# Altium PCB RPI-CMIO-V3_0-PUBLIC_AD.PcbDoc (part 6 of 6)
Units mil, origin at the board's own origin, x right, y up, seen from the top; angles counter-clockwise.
Board outline 3295.4 x 4105.44 mil, 6 copper layers (TOP, GNDT, PWRT, PWRB, GNDB, BOTTOM); 114 components, 152 nets, 703 pads, 476 vias.
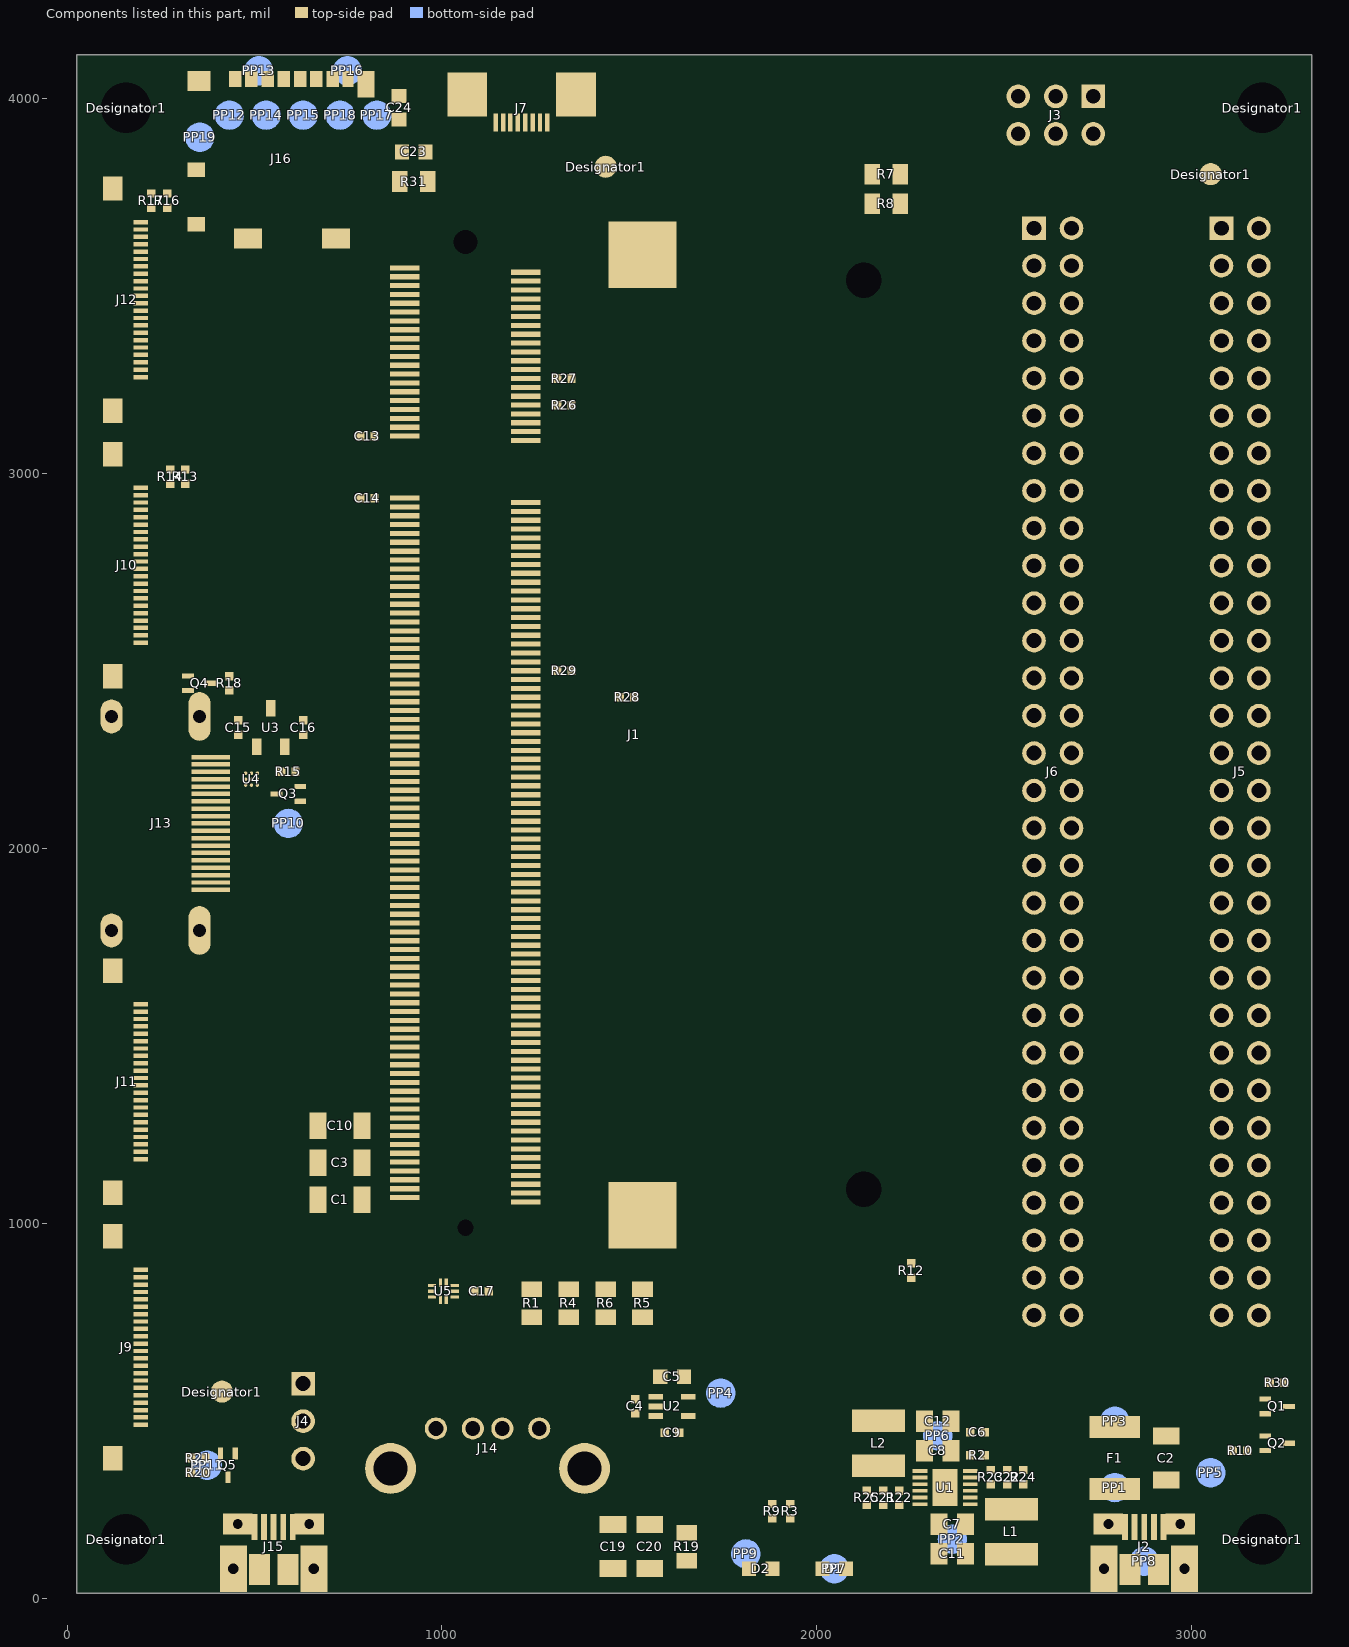
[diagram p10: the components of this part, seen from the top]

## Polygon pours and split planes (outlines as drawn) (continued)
CAM0_CN on BOTTOM "BOTTOM-CAM0_CN 1" (solid, pour order 1354): 1309.15,1716.41 ccw(c1310.77,1714.79) 1309.15,1713.18 1314.5,1707.84 1322.03,1714.79 1314.5,1721.75 1309.15,1716.41 ccw(c1310.77,1714.79)
DSI1_DN3 on BOTTOM "BOTTOM-DSI1_DN3" (solid, pour order 1355): 270.22,3516.35 ccw(c267.94,3516.35) 267.94,3518.63 260.38,3518.63 259.97,3508.39 270.22,3508.79 270.22,3516.35 ccw(c267.94,3516.35)
DSI1_DN3 on BOTTOM "BOTTOM-DSI1_DN3 1" (solid, pour order 1356): 1308.92,2141.63 ccw(c1310.53,2140.01) 1308.92,2138.4 1314.26,2133.05 1321.79,2140.01 1314.26,2146.97 1308.92,2141.63 ccw(c1310.53,2140.01)
GPIO20 on BOTTOM "BOTTOM-GPIO20" (solid, pour order 1357): 984.25,2594.49 ccw(c984.25,2598.43) 988.19,2598.43 988.19,2604.33 977.65,2605.03 978.35,2594.49 984.25,2594.49 ccw(c984.25,2598.43)
GPIO8 on BOTTOM "BOTTOM-GPIO8" (solid, pour order 1358): 992.13,3232.28 ccw(c992.13,3236.22) 996.06,3236.22 996.06,3242.13 985.52,3242.82 986.22,3232.28 992.13,3232.28 ccw(c992.13,3236.22)
DSI1_DN2 on BOTTOM "BOTTOM-DSI1_DN2" (solid, pour order 1359): 284.16,3455.57 ccw(c281.88,3455.57) 281.88,3457.85 274.32,3457.85 273.91,3447.61 284.16,3448.01 284.16,3455.57 ccw(c281.88,3455.57)
DSI1_DN2 on BOTTOM "BOTTOM-DSI1_DN2 1" (solid, pour order 1360): 1308.96,2070.61 ccw(c1310.57,2069) 1308.96,2067.39 1314.3,2062.04 1321.83,2069 1314.3,2075.96 1308.96,2070.61 ccw(c1310.57,2069)
DSI0_DP1 on BOTTOM "BOTTOM-DSI0_DP1" (solid, pour order 1361): 289.45,2511.87 ccw(c287.84,2510.25) 286.22,2511.87 280.88,2506.52 287.84,2498.99 294.8,2506.52 289.45,2511.87 ccw(c287.84,2510.25)
DSI0_DP1 on BOTTOM "BOTTOM-DSI0_DP1 1" (solid, pour order 1362): 732.6,2302.34 ccw(c732.6,2300.06) 730.32,2300.06 730.32,2292.5 740.56,2292.1 740.16,2302.34 732.6,2302.34 ccw(c732.6,2300.06)
GPIO15 on BOTTOM "BOTTOM-GPIO15" (solid, pour order 1363): 968.5,2783.47 ccw(c968.5,2787.4) 972.44,2787.4 972.44,2793.31 961.9,2794 962.6,2783.47 968.5,2783.47 ccw(c968.5,2787.4)
GPIO25 on BOTTOM "BOTTOM-GPIO25" (solid, pour order 1364): 1114.17,2429.13 ccw(c1114.17,2433.07) 1118.11,2433.07 1118.11,2438.98 1107.57,2439.67 1108.27,2429.13 1114.17,2429.13 ccw(c1114.17,2433.07)
DSI1_DN0 on BOTTOM "BOTTOM-DSI1_DN0" (solid, pour order 1365): 608.27,3278.41 ccw(c605.98,3278.41) 605.98,3280.69 598.42,3280.69 598.02,3270.44 608.27,3270.85 608.27,3278.41 ccw(c605.98,3278.41)
DSI1_DN0 on BOTTOM "BOTTOM-DSI1_DN0 1" (solid, pour order 1366): 1308.92,2283.36 ccw(c1310.53,2281.74) 1308.92,2280.13 1314.26,2274.79 1321.79,2281.74 1314.26,2288.7 1308.92,2283.36 ccw(c1310.53,2281.74)
GPIO17 on BOTTOM "BOTTOM-GPIO17" (solid, pour order 1367): 961.69,2712.6 ccw(c961.69,2716.53) 965.63,2716.53 965.63,2722.44 955.09,2723.14 955.79,2712.6 961.69,2712.6 ccw(c961.69,2716.53)
GPIO11 on BOTTOM "BOTTOM-GPIO11" (solid, pour order 1368): 961.69,3137.79 ccw(c961.69,3141.73) 965.63,3141.73 965.63,3147.64 955.09,3148.34 955.79,3137.79 961.69,3137.79 ccw(c961.69,3141.73)
GPIO22 on BOTTOM "BOTTOM-GPIO22" (solid, pour order 1369): 1039.37,2523.62 ccw(c1039.37,2527.56) 1043.31,2527.56 1043.31,2533.47 1032.77,2534.16 1033.47,2523.62 1039.37,2523.62 ccw(c1039.37,2527.56)
CD1_SCL on BOTTOM "BOTTOM-CD1_SCL" (solid, pour order 1370): 248.71,1679.95 ccw(c251.49,1677.16) 248.71,1674.38 252.88,1670.21 260.83,1677.16 252.88,1684.12 248.71,1679.95 ccw(c251.49,1677.16)
CD1_SCL on BOTTOM "BOTTOM-CD1_SCL 1" (solid, pour order 1371): 166.17,1556.41 ccw(c163.39,1553.63) 160.6,1556.41 156.43,1552.24 163.39,1544.29 170.34,1552.24 166.17,1556.41 ccw(c163.39,1553.63)
DSI1_CP on BOTTOM "BOTTOM-DSI1_CP" (solid, pour order 1372): 513.47,3412.22 ccw(c513.47,3414.51) 515.75,3414.51 515.75,3422.07 505.5,3422.47 505.91,3412.22 513.47,3412.22 ccw(c513.47,3414.51)
DSI1_CP on BOTTOM "BOTTOM-DSI1_CP 1" (solid, pour order 1373): 1308.96,2243.35 ccw(c1310.57,2241.73) 1308.96,2240.12 1314.3,2234.78 1321.83,2241.73 1314.3,2248.69 1308.96,2243.35 ccw(c1310.57,2241.73)
VDD_CORE on BOTTOM "BOTTOM-VDD_CORE" (solid, pour order 1374): 977.67,1288.55 ccw(c974.89,1291.34) 977.67,1294.12 973.5,1298.3 965.55,1291.34 973.5,1284.38 977.67,1288.55 ccw(c974.89,1291.34)
VDD_CORE on BOTTOM "BOTTOM-VDD_CORE 1" (solid, pour order 1375): 2023.62,1299.21 ccw(c2027.56,1299.21) 2027.56,1295.28 2033.47,1295.28 2034.16,1305.82 2023.62,1305.12 2023.62,1299.21 ccw(c2027.56,1299.21)
GPIO16 on BOTTOM "BOTTOM-GPIO16" (solid, pour order 1376): 990.16,2736.22 ccw(c990.16,2740.16) 994.1,2740.16 994.1,2746.06 983.56,2746.76 984.25,2736.22 990.16,2736.22 ccw(c990.16,2740.16)
DSI0_CP on BOTTOM "BOTTOM-DSI0_CP" (solid, pour order 1377): 127.91,2703.56 ccw(c127.91,2705.85) 130.19,2705.85 130.19,2713.41 119.94,2713.81 120.35,2703.56 127.91,2703.56 ccw(c127.91,2705.85)
DSI0_CP on BOTTOM "BOTTOM-DSI0_CP 1" (solid, pour order 1378): 689.87,2392.66 ccw(c691.49,2394.28) 693.1,2392.66 698.44,2398.01 691.49,2405.54 684.53,2398.01 689.87,2392.66 ccw(c691.49,2394.28)
GPIO14 on BOTTOM "BOTTOM-GPIO14" (solid, pour order 1379): 992.13,2807.09 ccw(c992.13,2811.02) 996.06,2811.02 996.06,2816.93 985.52,2817.63 986.22,2807.09 992.13,2807.09 ccw(c992.13,2811.02)
RUN on BOTTOM "BOTTOM-RUN" (solid, pour order 1380): 965.63,1334.65 ccw(c961.69,1334.65) 961.69,1338.58 955.79,1338.58 955.09,1328.04 965.63,1328.74 965.63,1334.65 ccw(c961.69,1334.65)
DSI1_DP1 on BOTTOM "BOTTOM-DSI1_DP1" (solid, pour order 1381): 281.88,3353.17 ccw(c281.88,3355.45) 284.16,3355.45 284.16,3363.01 273.91,3363.42 274.32,3353.17 281.88,3353.17 ccw(c281.88,3355.45)
DSI1_DP1 on BOTTOM "BOTTOM-DSI1_DP1 1" (solid, pour order 1382): 1308.92,2030.89 ccw(c1310.53,2029.28) 1308.92,2027.66 1314.26,2022.32 1321.79,2029.28 1314.26,2036.24 1308.92,2030.89 ccw(c1310.53,2029.28)
DSI1_DP3 on BOTTOM "BOTTOM-DSI1_DP3" (solid, pour order 1383): 267.94,3532.06 ccw(c267.94,3534.35) 270.22,3534.35 270.22,3541.91 259.97,3542.31 260.38,3532.06 267.94,3532.06 ccw(c267.94,3534.35)
DSI1_DP3 on BOTTOM "BOTTOM-DSI1_DP3 1" (solid, pour order 1384): 1308.92,2172.63 ccw(c1310.53,2171.01) 1308.92,2169.4 1314.26,2164.05 1321.79,2171.01 1314.26,2177.97 1308.92,2172.63 ccw(c1310.53,2171.01)
GPIO9 on BOTTOM "BOTTOM-GPIO9" (solid, pour order 1385): 968.5,3208.66 ccw(c968.5,3212.6) 972.44,3212.6 972.44,3218.5 961.9,3219.2 962.6,3208.66 968.5,3208.66 ccw(c968.5,3212.6)
CAM0_CP on BOTTOM "BOTTOM-CAM0_CP" (solid, pour order 1386): 147.79,623.58 ccw(c146.17,625.2) 147.79,626.81 142.44,632.15 134.91,625.2 142.44,618.24 147.79,623.58 ccw(c146.17,625.2)
CAM0_CP on BOTTOM "BOTTOM-CAM0_CP 1" (solid, pour order 1387): 1309.15,1747.45 ccw(c1310.77,1745.84) 1309.15,1744.22 1314.5,1738.88 1322.03,1745.84 1314.5,1752.79 1309.15,1747.45 ccw(c1310.77,1745.84)
CAM0_DN1 on BOTTOM "BOTTOM-CAM0_DN1" (solid, pour order 1388): 147.79,533.48 ccw(c146.17,535.1) 147.79,536.71 142.44,542.06 134.91,535.1 142.44,528.14 147.79,533.48 ccw(c146.17,535.1)
CAM0_DN1 on BOTTOM "BOTTOM-CAM0_DN1 1" (solid, pour order 1389): 1309.15,1645.54 ccw(c1310.77,1643.93) 1309.15,1642.31 1314.5,1636.97 1322.03,1643.93 1314.5,1650.88 1309.15,1645.54 ccw(c1310.77,1643.93)
DSI1_CN on BOTTOM "BOTTOM-DSI1_CN" (solid, pour order 1390): 515.75,3396.51 ccw(c513.47,3396.51) 513.47,3398.79 505.91,3398.79 505.5,3388.55 515.75,3388.95 515.75,3396.51 ccw(c513.47,3396.51)
DSI1_CN on BOTTOM "BOTTOM-DSI1_CN 1" (solid, pour order 1391): 1308.96,2212.35 ccw(c1310.57,2210.73) 1308.96,2209.12 1314.3,2203.78 1321.83,2210.73 1314.3,2217.69 1308.96,2212.35 ccw(c1310.57,2210.73)
GPIO18 on BOTTOM "BOTTOM-GPIO18" (solid, pour order 1392): 992.13,2665.35 ccw(c992.13,2669.29) 996.06,2669.29 996.06,2675.2 985.52,2675.89 986.22,2665.35 992.13,2665.35 ccw(c992.13,2669.29)
DSI1_DP2 on BOTTOM "BOTTOM-DSI1_DP2" (solid, pour order 1393): 281.88,3471.28 ccw(c281.88,3473.57) 284.16,3473.57 284.16,3481.13 273.91,3481.53 274.32,3471.28 281.88,3471.28 ccw(c281.88,3473.57)
DSI1_DP2 on BOTTOM "BOTTOM-DSI1_DP2 1" (solid, pour order 1394): 1308.96,2101.61 ccw(c1310.57,2100) 1308.96,2098.39 1314.3,2093.04 1321.83,2100 1314.3,2106.96 1308.96,2101.61 ccw(c1310.57,2100)
DSI0_CN on BOTTOM "BOTTOM-DSI0_CN" (solid, pour order 1395): 130.19,2687.85 ccw(c127.91,2687.85) 127.91,2690.13 120.35,2690.13 119.94,2679.89 130.19,2680.29 130.19,2687.85 ccw(c127.91,2687.85)
DSI0_CN on BOTTOM "BOTTOM-DSI0_CN 1" (solid, pour order 1396): 702.6,2383.16 ccw(c704.22,2381.55) 702.6,2379.94 707.94,2374.6 715.48,2381.55 707.94,2388.51 702.6,2383.16 ccw(c704.22,2381.55)
GPIO21 on BOTTOM "BOTTOM-GPIO21" (solid, pour order 1397): 961.69,2570.87 ccw(c961.69,2574.8) 965.63,2574.8 965.63,2580.71 955.09,2581.41 955.79,2570.87 961.69,2570.87 ccw(c961.69,2574.8)
USB_OTGID on BOTTOM "BOTTOM-USB_OTGID" (solid, pour order 1398): 1582,1386.98 ccw(c1579.22,1389.76) 1582,1392.55 1577.83,1396.72 1569.88,1389.76 1577.83,1382.81 1582,1386.98 ccw(c1579.22,1389.76)
USB_OTGID on BOTTOM "BOTTOM-USB_OTGID 1" (solid, pour order 1399): 2175.2,1273.62 ccw(c2175.2,1269.68) 2171.26,1269.68 2171.26,1263.78 2181.8,1263.08 2181.1,1273.62 2175.2,1273.62 ccw(c2175.2,1269.68)
GPIO13 on BOTTOM "BOTTOM-GPIO13" (solid, pour order 1400): 968.5,2854.33 ccw(c968.5,2858.27) 972.44,2858.27 972.44,2864.17 961.9,2864.87 962.6,2854.33 968.5,2854.33 ccw(c968.5,2858.27)
CAM0_DP0 on BOTTOM "BOTTOM-CAM0_DP0" (solid, pour order 1401): 268.2,713.09 ccw(c266.58,711.48) 264.97,713.09 259.63,707.75 266.58,700.22 273.54,707.75 268.2,713.09 ccw(c266.58,711.48)
CAM0_DP0 on BOTTOM "BOTTOM-CAM0_DP0 1" (solid, pour order 1402): 1308.96,1816.58 ccw(c1310.57,1814.96) 1308.96,1813.35 1314.3,1808 1321.83,1814.96 1314.3,1821.92 1308.96,1816.58 ccw(c1310.57,1814.96)
GPIO10 on BOTTOM "BOTTOM-GPIO10" (solid, pour order 1403): 992.13,3161.42 ccw(c992.13,3165.35) 996.06,3165.35 996.06,3171.26 985.52,3171.96 986.22,3161.42 992.13,3161.42 ccw(c992.13,3165.35)
GPIO5 on BOTTOM "BOTTOM-GPIO5" (solid, pour order 1404): 981.61,3357.45 ccw(c978.82,3360.24) 981.61,3363.02 977.43,3367.19 969.49,3360.24 977.43,3353.28 981.61,3357.45 ccw(c978.82,3360.24)
CAM0_DN0 on BOTTOM "BOTTOM-CAM0_DN0" (solid, pour order 1405): 299.24,713.09 ccw(c297.63,711.48) 296.01,713.09 290.67,707.75 297.63,700.22 304.58,707.75 299.24,713.09 ccw(c297.63,711.48)
CAM0_DN0 on BOTTOM "BOTTOM-CAM0_DN0 1" (solid, pour order 1406): 1308.96,1785.53 ccw(c1310.57,1783.92) 1308.96,1782.3 1314.3,1776.96 1321.83,1783.92 1314.3,1790.87 1308.96,1785.53 ccw(c1310.57,1783.92)
CAM0_DP1 on BOTTOM "BOTTOM-CAM0_DP1" (solid, pour order 1407): 147.79,564.53 ccw(c146.17,566.14) 147.79,567.76 142.44,573.1 134.91,566.14 142.44,559.18 147.79,564.53 ccw(c146.17,566.14)
CAM0_DP1 on BOTTOM "BOTTOM-CAM0_DP1 1" (solid, pour order 1408): 1309.15,1676.58 ccw(c1310.77,1674.97) 1309.15,1673.35 1314.5,1668.01 1322.03,1674.97 1314.5,1681.93 1309.15,1676.58 ccw(c1310.77,1674.97)
DSI0_DN0 on BOTTOM "BOTTOM-DSI0_DN0" (solid, pour order 1409): 124.6,2572.03 ccw(c124.6,2569.74) 122.32,2569.74 122.32,2562.18 132.57,2561.78 132.16,2572.03 124.6,2572.03 ccw(c124.6,2569.74)
DSI0_DN0 on BOTTOM "BOTTOM-DSI0_DN0 1" (solid, pour order 1410): 730.32,2247.19 ccw(c732.6,2247.19) 732.6,2244.91 740.16,2244.91 740.56,2255.15 730.32,2254.75 730.32,2247.19 ccw(c732.6,2247.19)
DSI1_DN1 on BOTTOM "BOTTOM-DSI1_DN1" (solid, pour order 1411): 284.16,3337.46 ccw(c281.88,3337.46) 281.88,3339.74 274.32,3339.74 273.91,3329.49 284.16,3329.9 284.16,3337.46 ccw(c281.88,3337.46)
DSI1_DN1 on BOTTOM "BOTTOM-DSI1_DN1 1" (solid, pour order 1412): 1308.92,1999.89 ccw(c1310.53,1998.28) 1308.92,1996.66 1314.26,1991.32 1321.79,1998.28 1314.26,2005.24 1308.92,1999.89 ccw(c1310.53,1998.28)
GPIO27 on BOTTOM "BOTTOM-GPIO27" (solid, pour order 1413): 1159.45,2358.27 ccw(c1159.45,2362.2) 1163.39,2362.2 1163.39,2368.11 1152.85,2368.81 1153.54,2358.27 1159.45,2358.27 ccw(c1159.45,2362.2)
GPIO23 on BOTTOM "BOTTOM-GPIO23" (solid, pour order 1414): 1009.84,2500 ccw(c1009.84,2503.94) 1013.78,2503.94 1013.78,2509.84 1003.24,2510.54 1003.94,2500 1009.84,2500 ccw(c1009.84,2503.94)
GPIO19 on BOTTOM "BOTTOM-GPIO19" (solid, pour order 1415): 961.69,2641.73 ccw(c961.69,2645.67) 965.63,2645.67 965.63,2651.58 955.09,2652.27 955.79,2641.73 961.69,2641.73 ccw(c961.69,2645.67)
DSI0_DP0 on BOTTOM "BOTTOM-DSI0_DP0" (solid, pour order 1416): 122.32,2587.74 ccw(c124.6,2587.74) 124.6,2585.46 132.16,2585.46 132.57,2595.7 122.32,2595.3 122.32,2587.74 ccw(c124.6,2587.74)
DSI0_DP0 on BOTTOM "BOTTOM-DSI0_DP0 1" (solid, pour order 1417): 732.6,2231.48 ccw(c732.6,2229.19) 730.32,2229.19 730.32,2221.63 740.56,2221.23 740.16,2231.48 732.6,2231.48 ccw(c732.6,2229.19)
GPIO12 on BOTTOM "BOTTOM-GPIO12" (solid, pour order 1418): 988.19,2877.95 ccw(c988.19,2881.89) 992.13,2881.89 992.13,2887.8 981.59,2888.49 982.28,2877.95 988.19,2877.95 ccw(c988.19,2881.89)
no net on Top Overlay (solid): 1972.44,114.17 ccw(c1980.32,114.17) 1980.32,106.3 ccw(c1980.32,114.17) 1988.19,114.17 ccw(c1980.32,114.17) 1980.32,122.05 ccw(c1980.32,114.17)
no net on Top Overlay (solid): 1775.59,114.17 ccw(c1783.47,114.17) 1783.47,106.3 ccw(c1783.47,114.17) 1791.34,114.17 ccw(c1783.47,114.17) 1783.47,122.05 ccw(c1783.47,114.17)
no net on Top Overlay (solid): 2244.09,358.27 ccw(c2250,358.27) 2250,352.36 ccw(c2250,358.27) 2255.91,358.27 ccw(c2250,358.27) 2250,364.17 ccw(c2250,358.27)
no net on Top Paste (solid): 614.17,114.17 562.99,114.17 562.99,82.68 614.17,82.68
no net on Top Paste (solid): 614.17,70.87 562.99,70.87 562.99,39.37 614.17,39.37
no net on Top Paste (solid): 539.37,70.87 488.19,70.87 488.19,39.37 539.37,39.37
no net on Top Paste (solid): 539.37,114.17 488.19,114.17 488.19,82.68 539.37,82.68
no net on Top Paste (solid): 700.79,157.48 637.8,157.48 637.8,133.86 700.79,133.86
no net on Top Paste (solid): 464.57,157.48 401.58,157.48 401.58,133.86 464.57,133.86
no net on Top Paste (solid): 681.1,122.05 637.8,122.05 637.8,39.37 681.1,39.37
no net on Top Paste (solid): 464.57,122.05 421.26,122.05 421.26,39.37 464.57,39.37
no net on Top Paste (solid): 685.04,224.41 629.92,224.41 629.92,173.23 685.04,173.23
no net on Top Paste (solid): 472.44,224.41 417.32,224.41 417.32,173.23 472.44,173.23
no net on Top Paste (solid): 2937.01,114.17 2885.83,114.17 2885.83,82.68 2937.01,82.68
no net on Top Paste (solid): 2937.01,70.87 2885.83,70.87 2885.83,39.37 2937.01,39.37
no net on Top Paste (solid): 2862.2,70.87 2811.02,70.87 2811.02,39.37 2862.2,39.37
no net on Top Paste (solid): 2862.2,114.17 2811.02,114.17 2811.02,82.68 2862.2,82.68
no net on Top Paste (solid): 3023.62,157.48 2960.63,157.48 2960.63,133.86 3023.62,133.86
no net on Top Paste (solid): 2787.4,157.48 2724.41,157.48 2724.41,133.86 2787.4,133.86
no net on Top Paste (solid): 3003.94,122.05 2960.63,122.05 2960.63,39.37 3003.94,39.37
no net on Top Paste (solid): 2787.4,122.05 2744.1,122.05 2744.1,39.37 2787.4,39.37
no net on Top Paste (solid): 3007.87,224.41 2952.76,224.41 2952.76,173.23 3007.87,173.23
no net on Top Paste (solid): 2795.28,224.41 2740.16,224.41 2740.16,173.23 2795.28,173.23
no net on Top Paste (solid): 2370.08,287.4 2314.96,287.4 2314.96,251.97 2370.08,251.97
no net on Top Paste (solid): 2370.08,338.58 2314.96,338.58 2314.96,303.15 2370.08,303.15
no net on Top Solder (solid): 1379.92,3818.9 ccw(c1437.01,3818.9) 1437.01,3761.81 ccw(c1437.01,3818.9) 1494.1,3818.9 ccw(c1437.01,3818.9) 1437.01,3875.98 ccw(c1437.01,3818.9)
no net on Top Solder (solid): 2994.1,3799.21 ccw(c3051.18,3799.21) 3051.18,3742.13 ccw(c3051.18,3799.21) 3108.27,3799.21 ccw(c3051.18,3799.21) 3051.18,3856.3 ccw(c3051.18,3799.21)
no net on Top Solder (solid): 356.3,551.18 ccw(c413.39,551.18) 413.39,494.1 ccw(c413.39,551.18) 470.47,551.18 ccw(c413.39,551.18) 413.39,608.27 ccw(c413.39,551.18)
no net on Top Solder (solid): 704.72,226.58 625.98,226.58 625.98,169.49 704.72,169.49
no net on Top Solder (solid): 704.72,131.89 704.72,159.45 632.87,159.45 632.87,35.43 684.06,35.43 684.06,131.89
no net on Top Solder (solid): 397.64,131.89 397.64,159.45 469.49,159.45 469.49,35.43 418.31,35.43 418.31,131.89
no net on Top Solder (solid): 476.38,226.58 397.64,226.58 397.64,169.49 476.38,169.49
no net on Top Solder (solid): 3027.56,226.58 2948.82,226.58 2948.82,169.49 3027.56,169.49
no net on Top Solder (solid): 3027.56,131.89 3027.56,159.45 2955.71,159.45 2955.71,35.43 3006.89,35.43 3006.89,131.89
no net on Top Solder (solid): 2720.47,131.89 2720.47,159.45 2792.32,159.45 2792.32,35.43 2741.14,35.43 2741.14,131.89
no net on Top Solder (solid): 2799.21,226.58 2720.47,226.58 2720.47,169.49 2799.21,169.49
no net on Keep-Out Layer (solid): 2015.68,3515.75 ccw(c2125.98,3515.75) 2125.98,3405.44 ccw(c2125.98,3515.75) 2236.29,3515.75 ccw(c2125.98,3515.75) 2125.98,3626.05 ccw(c2125.98,3515.75)
no net on Keep-Out Layer (solid): 2015.75,1090.55 ccw(c2125.98,1090.55) 2125.98,980.32 ccw(c2125.98,1090.55) 2236.22,1090.55 ccw(c2125.98,1090.55) 2125.98,1200.79 ccw(c2125.98,1090.55)
no net on Keep-Out Layer (solid): 3047.24,157.48 ccw(c3188.98,157.48) 3188.98,15.75 ccw(c3188.98,157.48) 3330.71,157.48 ccw(c3188.98,157.48) 3188.98,299.21 ccw(c3188.98,157.48)
no net on Keep-Out Layer (solid): 15.75,157.48 ccw(c157.48,157.48) 157.48,15.75 ccw(c157.48,157.48) 299.21,157.48 ccw(c157.48,157.48) 157.48,299.21 ccw(c157.48,157.48)
no net on Keep-Out Layer (solid): 3047.24,3976.38 ccw(c3188.98,3976.38) 3188.98,3834.65 ccw(c3188.98,3976.38) 3330.71,3976.38 ccw(c3188.98,3976.38) 3188.98,4118.11 ccw(c3188.98,3976.38)
no net on Keep-Out Layer (solid): 15.75,3976.38 ccw(c157.48,3976.38) 157.48,3834.65 ccw(c157.48,3976.38) 299.21,3976.38 ccw(c157.48,3976.38) 157.48,4118.11 ccw(c157.48,3976.38)

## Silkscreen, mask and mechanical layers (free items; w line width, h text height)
Top Overlay:
  lines w5.91: 2460.63,1909.45 2440.95,1909.45 2440.95,3700.79 2460.63,3700.79 ; 2574.8,346.46 2606.3,346.46 2641.73,381.89 ; 2952.76,905.51 2933.07,905.51 2933.07,3700.79 2952.76,3700.79
  text "TOP COMPONENT LEGEND" at 472.44,4763.78 h45.35
  text "1V8" at 2618.11,4074.8 h31.5
  text "3V3" at 2724.41,4074.8 h31.5
  text "Compute Module IO Board V3.0" at 1909.45,4015.75 h37.8
  text "VG0 SELCT" at 3035.43,3988.19 h31.5
  text "(c) Raspberry Pi 2014/15" at 1929.13,3897.64 h37.8
  text "VG1 SELCT" at 3035.43,3885.83 h31.5
  text "VC JTAG" at 1212.6,3842.52 h37.8
  text "1V8" at 2618.11,3807.09 h31.5
  text "3V3" at 2724.41,3807.09 h31.5
  text "GPIOx BANK 1" at 2421.26,3681.1 h31.5 r90
  text "GPIOx BANK 0" at 2913.39,3681.1 h31.5 r90
  text "28" at 2513.39,3638.58 h31.5
  text "GND" at 2750.39,3638.58 h31.5
  text "0" at 3010.24,3638.58 h31.5
  text "GND" at 3251.18,3638.58 h31.5
  text "29" at 2513.39,3538.58 h31.5
  text "5V0" at 2750.39,3538.58 h31.5
  text "1" at 3010.24,3538.58 h31.5
  text "5V0" at 3251.18,3538.58 h31.5
  text "SD CARD ONLY FOR" at 551.18,3484.25 h37.8
  text "30" at 2513.39,3438.58 h31.5
  text "GND" at 2750.39,3438.58 h31.5
  text "2" at 3010.24,3438.58 h31.5
  text "GND" at 3251.18,3438.58 h31.5
  text "MODULES WITHOUT" at 551.18,3405.51 h37.8
  text "31" at 2513.39,3338.58 h31.5
  text "3V3" at 2750.39,3338.58 h31.5
  text "3" at 3010.24,3338.58 h31.5
  text "3V3" at 3251.18,3338.58 h31.5
  text "ON-BOARD FLASH" at 551.18,3326.77 h37.8
  text "32" at 2513.39,3238.58 h31.5
  text "GND" at 2750.39,3238.58 h31.5
  text "4" at 3010.24,3238.58 h31.5
  text "GND" at 3251.18,3238.58 h31.5
  text "DISP1" at 354.33,3208.66 h45.35
  text "33" at 2513.39,3138.58 h31.5
  text "1V8" at 2750.39,3138.58 h31.5
  text "5" at 3010.24,3138.58 h31.5
  text "1V8" at 3251.18,3138.58 h31.5
  text "34" at 2513.39,3038.58 h31.5
  text "GND" at 2750.39,3038.58 h31.5
  text "6" at 3010.24,3038.58 h31.5
  text "GND" at 3251.18,3038.58 h31.5
  text "35" at 2513.39,2938.58 h31.5
  text "VG1" at 2750.39,2938.58 h31.5
  text "7" at 3010.24,2938.58 h31.5
  text "VG0" at 3251.18,2938.58 h31.5
  text "36" at 2513.39,2838.58 h31.5
  text "GND" at 2750.39,2838.58 h31.5
  text "8" at 3010.24,2838.58 h31.5
  text "GND" at 3251.18,2838.58 h31.5
  text "DISP0" at 314.96,2755.91 h45.35 r90
  text "37" at 2513.39,2738.58 h31.5
  text "3V3" at 2750.39,2738.58 h31.5
  text "9" at 3010.24,2738.58 h31.5
  text "3V3" at 3251.18,2738.58 h31.5
  text "38" at 2513.39,2638.58 h31.5
  text "GND" at 2750.39,2638.58 h31.5
  text "10" at 3010.24,2638.58 h31.5
  text "GND" at 3251.18,2638.58 h31.5
  text "39" at 2513.39,2538.58 h31.5
  text "1V8" at 2750.39,2538.58 h31.5
  text "11" at 3010.24,2538.58 h31.5
  text "1V8" at 3251.18,2538.58 h31.5
  text "40" at 2513.39,2438.58 h31.5
  text "GND" at 2750.39,2438.58 h31.5
  text "12" at 3010.24,2438.58 h31.5
  text "GND" at 3251.18,2438.58 h31.5
  text "41" at 2513.39,2338.58 h31.5
  text "VG1" at 2750.39,2338.58 h31.5
  text "13" at 3010.24,2338.58 h31.5
  text "VG0" at 3251.18,2338.58 h31.5
  text "RASPBERRY PI COMPUTE MODULE" at 1692.91,2303.15 h65.31 r90
  text "OR COMPUTE MODULE 3" at 1830.71,2303.15 h65.31 r90
  text "42" at 2513.39,2238.58 h31.5
  text "GND" at 2750.39,2238.58 h31.5
  text "14" at 3010.24,2238.58 h31.5
  text "GND" at 3251.18,2238.58 h31.5
  text "43" at 2513.39,2138.58 h31.5
  text "3V3" at 2750.39,2138.58 h31.5
  text "15" at 3010.24,2138.58 h31.5
  text "3V3" at 3251.18,2138.58 h31.5
  text "44" at 2513.39,2038.58 h31.5
  text "GND" at 2750.39,2038.58 h31.5
  text "16" at 3010.24,2038.58 h31.5
  text "GND" at 3251.18,2038.58 h31.5
  text "45" at 2513.39,1938.58 h31.5
  text "1V8" at 2750.39,1938.58 h31.5
  text "17" at 3010.24,1938.58 h31.5
  text "1V8" at 3251.18,1938.58 h31.5
  text "CD1_SDA" at 2512.6,1838.58 h31.5
  text "GND" at 2750.39,1838.58 h31.5
  text "18" at 3010.24,1838.58 h31.5
  text "GND" at 3251.18,1838.58 h31.5
  text "CD1_SCL" at 2512.6,1738.58 h31.5
  text "VG1" at 2750.39,1738.58 h31.5
  text "19" at 3010.24,1738.58 h31.5
  text "VG0" at 3251.18,1738.58 h31.5
  text "CAM1_IO1" at 2512.6,1638.58 h31.5
  text "GND" at 2750.39,1638.58 h31.5
  text "20" at 3010.24,1638.58 h31.5
  text "GND" at 3251.18,1638.58 h31.5
  text "CAM1_IO0" at 2512.6,1538.58 h31.5
  text "3V3" at 2750.39,1538.58 h31.5
  text "21" at 3010.24,1538.58 h31.5
  text "3V3" at 3251.18,1538.58 h31.5
  text "CD0_SDA" at 2512.6,1438.58 h31.5
  text "GND" at 2750.39,1438.58 h31.5
  text "22" at 3010.24,1438.58 h31.5
  text "GND" at 3251.18,1438.58 h31.5
  text "CAM1" at 314.96,1377.95 h45.35 r90
  text "CD0_SCL" at 2512.6,1338.58 h31.5
  text "1V8" at 2750.39,1338.58 h31.5
  text "23" at 3010.24,1338.58 h31.5
  text "1V8" at 3251.18,1338.58 h31.5
  text "CAM0_IO1" at 2512.6,1238.58 h31.5
  text "GND" at 2750.39,1238.58 h31.5
  text "24" at 3010.24,1238.58 h31.5
  text "GND" at 3251.18,1238.58 h31.5
  text "CAM0_IO0" at 2512.6,1138.58 h31.5
  text "VG1" at 2750.39,1138.58 h31.5
  text "25" at 3010.24,1138.58 h31.5
  text "VG0" at 3251.18,1138.58 h31.5
  text "VDD_CORE" at 2513.39,1038.58 h31.5
  text "GND" at 2750.39,1038.58 h31.5
  text "26" at 3010.24,1038.58 h31.5
  text "GND" at 3251.18,1038.58 h31.5
  text "USB_" at 2488.19,968.5 h31.5
  text "5V0" at 2750.39,938.58 h31.5
  text "27" at 3010.24,938.58 h31.5
  text "5V0" at 3251.18,938.58 h31.5
  text "OTGID" at 2515.75,909.45 h31.5
  text "GND" at 2513.39,838.58 h31.5
  text "RUN" at 3010.24,838.58 h31.5
  text "GND" at 3251.18,838.58 h31.5
  text "GND" at 2751.97,834.65 h31.5
  text "Made in the UK" at 1862.2,767.72 h37.8
  text "GND" at 2751.97,740.16 h31.5
  text "NC" at 2940.95,740.16 h31.5
  text "TVDAC" at 2513.39,738.58 h31.5
  text "GND" at 3251.18,738.58 h31.5
  text "USB SLAVE" at 744.1,704.72 h31.5
  text "CAM0" at 314.96,669.29 h45.35 r90
  text "BOOT ENABLE" at 775.59,649.61 h31.5
  text "EN" at 740.16,507.87 h31.5
  text "DIS" at 767.72,397.64 h31.5
  text "USB SLAVE" at 370.08,153.54 h37.8 r90
  text "USB HOST" at 826.77,137.8 h37.8 r90
  text "ACT" at 1850.39,137.8 h37.8
  text "PWR" at 2047.24,137.8 h37.8
  text "POWER IN" at 2696.85,137.8 h37.8 r90
Bottom Overlay:
  text "BOTTOM COMPONENT LEGEND" at 472.44,4488.19 h45.35
Top Paste:
  text "TOP PASTE MASK" at 472.44,4842.52 h45.35
Top Solder:
  text "TOP SOLDER MASK" at 472.44,4685.04 h45.35
Bottom Solder:
  text "BOTTOM SOLDER MASK" at 472.44,4606.3 h45.35
Mechanical 1:
  lines w5: 0,0 3346.46,0 3346.46,4133.86 0,4133.86 0,0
